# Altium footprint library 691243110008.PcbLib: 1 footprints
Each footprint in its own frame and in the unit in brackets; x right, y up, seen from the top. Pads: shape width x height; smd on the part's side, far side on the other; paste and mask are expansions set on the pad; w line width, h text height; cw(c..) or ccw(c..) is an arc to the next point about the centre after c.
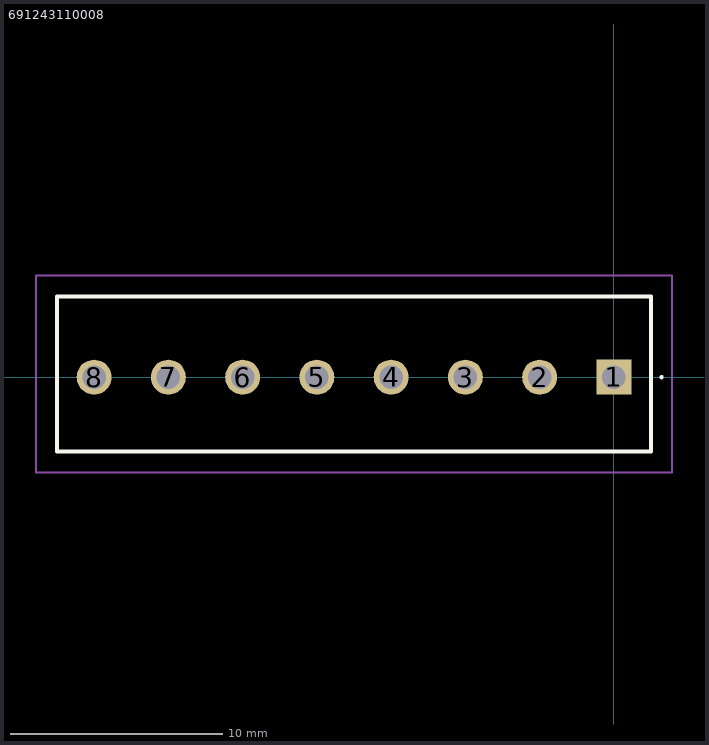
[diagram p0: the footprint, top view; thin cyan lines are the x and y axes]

## 691243110008 [mm]
pads (8):
  rect 1.65x1.65 hole 1.1: 1(0,0)
  round 1.65 hole 1.1: 2(-3.5,0) 3(-7,0) 4(-10.5,0) 5(-14,0) 6(-17.5,0) 7(-21,0) 8(-24.5,0)
Top Overlay:
  lines w0.1: 2.2,0 2.2,0 ; 2.2,0 ccw(c2.25,0) 2.3,0 ; 2.2,0 cw(c2.25,0) 2.3,0 ; 2.3,0 2.3,0
  lines w0.2: -26.25,-3.5 -26.25,3.8 1.75,3.8 1.75,-3.5 -26.25,-3.5
Mechanical 15:
  lines w0.1: -26.25,-3.5 1.75,-3.5 1.75,3.8 -26.25,3.8 -26.25,-3.5
Mechanical 20:
  lines w0.1: -27.25,-4.5 2.75,-4.5 2.75,4.8 -27.25,4.8 -27.25,-4.5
